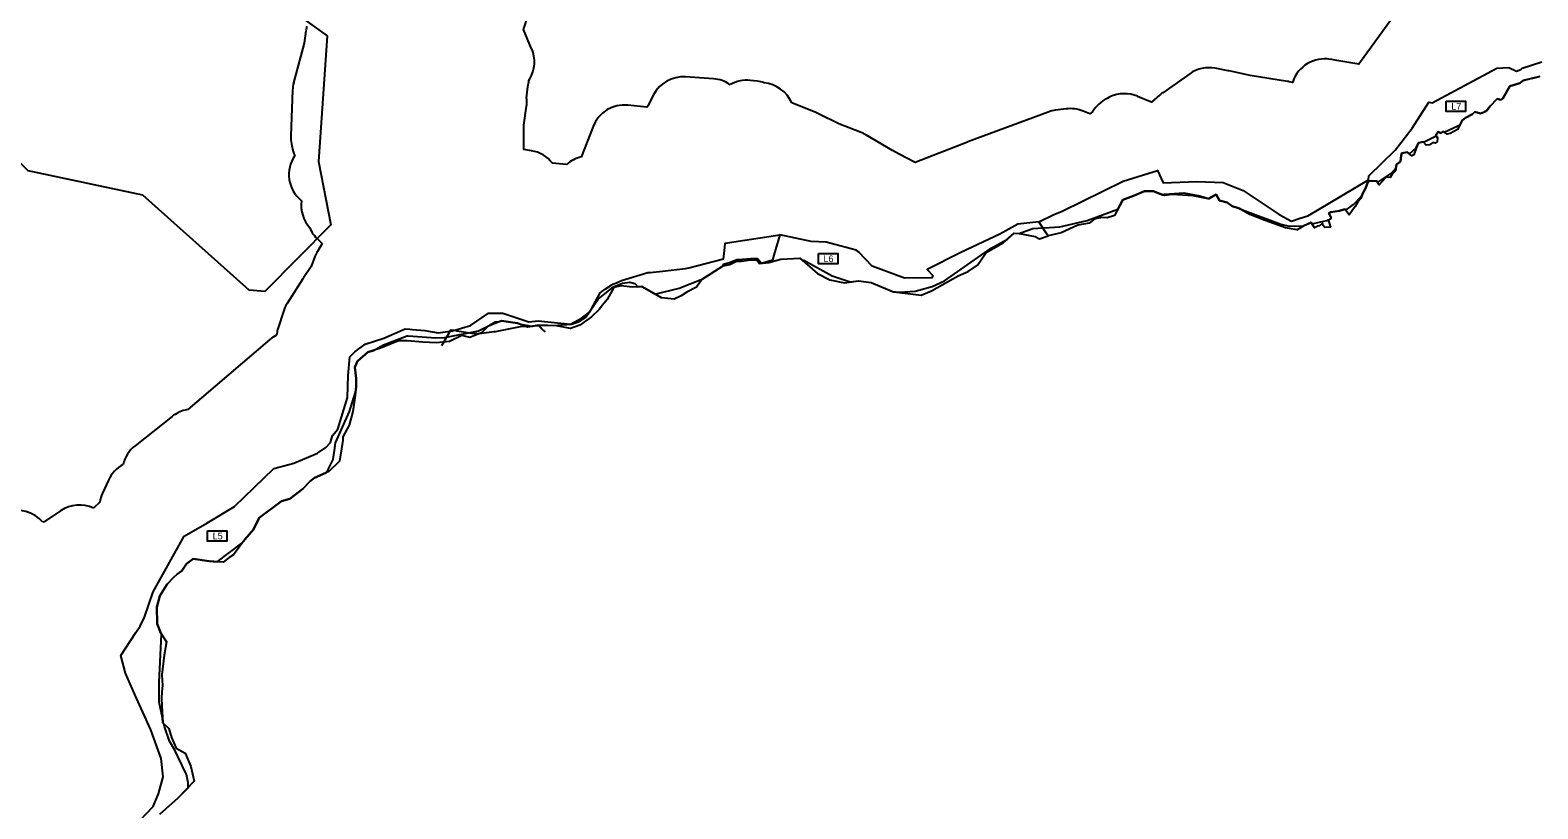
# Model space of a CAD drawing. Extents: x -547623 to -532764, y -1096714 to -1086523.
# Drawn here: x -544003 to -541756, y -1095554 to -1094393 of the extents above; entities that cross this region are included whole.
import ezdxf

# ---------------------------------------------------------------- set-up
doc = ezdxf.new("R2010")
doc.units = 0
for name, color, linetype in [('Vrstva 22', 7, 'Continuous'), ('Vrstva 23', 7, 'Continuous'), ('Vrstva 32', 7, 'Continuous'), ('Vrstva 33', 7, 'Continuous'), ('Vrstva 36', 7, 'Continuous')]:
    doc.layers.add(name, color=color, linetype=linetype)

msp = doc.modelspace()

# ---------------------------------------------------------------- linework, layer by layer
at = {"layer": 'Vrstva 22'}
for points in [[(-543560.2, -1094401.9), (-543572.9, -1094589), (-543554.8, -1094683.6), (-543653.3, -1094783), (-543676.2, -1094781), (-543835.1, -1094639.3), (-544005.7, -1094603.1), (-544067, -1094543.3), (-544325.4, -1094603.1), (-544346.2, -1094593.4), (-544353.7, -1094422.2), (-544152.6, -1094360.6), (-544163.2, -1094317.9), (-544141.9, -1094287.2), (-544146.7, -1094205.7), (-543991.6, -1094091.9), (-543560.2, -1094401.9)], [(-543809.7, -1095562), (-543782.5, -1095538.1), (-543767.4, -1095522.3), (-543767.1, -1095514.9), (-543769.7, -1095502.6), (-543782.6, -1095476), (-543787.2, -1095466.4), (-543795.3, -1095453.2), (-543802.7, -1095431.2), (-543803.6, -1095427), (-543804.9, -1095425.8), (-543805.5, -1095418), (-543810.4, -1095394.8), (-543810.6, -1095367.2), (-543810.5, -1095365.7), (-543807.1, -1095293.4), (-543808.1, -1095291.9), (-543813.3, -1095278.2), (-543814.2, -1095253.2), (-543809.7, -1095236.4), (-543798.5, -1095218.8), (-543789.3, -1095209), (-543783.6, -1095204.3), (-543776.7, -1095199.2), (-543769.6, -1095188.9), (-543759.7, -1095181.3), (-543736.2, -1095184.9), (-543723.9, -1095185.6), (-543687.1, -1095158), (-543683.1, -1095152.5), (-543670.1, -1095137.4), (-543661.4, -1095120), (-543628, -1095095.2), (-543615.8, -1095091.8), (-543596.4, -1095077), (-543585.6, -1095065.3), (-543578.9, -1095060.6), (-543562.3, -1095053.3), (-543558.8, -1095048.2), (-543551, -1095033), (-543549.4, -1095020), (-543547.9, -1095008.3), (-543527, -1094961.6), (-543517.8, -1094932.9), (-543516.9, -1094925.6), (-543517.1, -1094912.3), (-543518.7, -1094895.4), (-543515, -1094886.5), (-543499.6, -1094873.2), (-543491.3, -1094870.7), (-543476.1, -1094862.1), (-543440.9, -1094849), (-543440.8, -1094848.8), (-543439.3, -1094848.9), (-543398.1, -1094851.9), (-543385, -1094851.2), (-543334.8, -1094841.6), (-543317.9, -1094832.8), (-543309.1, -1094828.2), (-543303.3, -1094827.7), (-543300.5, -1094826.6), (-543276.6, -1094829.8), (-543272.1, -1094831.6), (-543255.6, -1094834.5), (-543254, -1094834.5), (-543244.5, -1094832.9), (-543223.2, -1094833.6), (-543196.2, -1094831.5), (-543185.8, -1094828.2), (-543174.6, -1094821.1), (-543156.1, -1094794.3), (-543133.5, -1094776.1), (-543120, -1094770.4), (-543109, -1094768.9), (-543101.4, -1094771), (-543097.4, -1094775.8), (-543091.3, -1094775.4), (-543074, -1094785.5), (-543071.6, -1094786.8), (-543035.5, -1094777.7), (-543000.4, -1094763.9), (-542970, -1094744.8), (-542959.8, -1094742.5), (-542950.1, -1094737.7), (-542942.8, -1094737.7), (-542929.1, -1094735.8), (-542919.9, -1094736.3), (-542915.9, -1094741.3), (-542901.9, -1094739.7), (-542883.9, -1094734.4), (-542855.6, -1094733.1), (-542852.6, -1094735.8), (-542848.8, -1094736.5), (-542807.3, -1094759.3), (-542780.5, -1094768.5), (-542768.2, -1094766.8), (-542749.4, -1094769.5), (-542717.7, -1094782.6), (-542707.1, -1094783.6), (-542683.6, -1094782.4), (-542658.5, -1094775.4), (-542640.1, -1094767.1), (-542570.7, -1094718), (-542546, -1094704.6), (-542536.2, -1094696), (-542528.8, -1094696.6), (-542528.6, -1094696.6), (-542521.1, -1094693.2), (-542508.7, -1094689.1), (-542468, -1094686.4), (-542427.4, -1094676.8), (-542381.9, -1094660), (-542374.5, -1094646.2), (-542358.2, -1094640.2), (-542342.1, -1094633.3), (-542329.2, -1094633.2), (-542315.4, -1094638.5), (-542312.3, -1094637.9), (-542283.6, -1094635.9), (-542259.4, -1094640.1), (-542246.5, -1094644.1), (-542245.9, -1094644.3), (-542235.2, -1094638.1), (-542230.4, -1094647.4), (-542218.9, -1094650.2), (-542211.2, -1094655.4), (-542200.6, -1094659.3), (-542199.9, -1094659.7), (-542138.7, -1094682.6), (-542126.6, -1094685.4), (-542105.5, -1094684.7), (-542103, -1094684.1), (-542093.8, -1094680.2), (-542092.7, -1094681.9), (-542070.3, -1094677), (-542065, -1094674.3), (-542063.8, -1094672.9), (-542067.4, -1094666.2), (-542064.2, -1094664.5), (-542051.3, -1094662.4), (-542043.3, -1094659.9), (-542042, -1094661.6), (-542030.4, -1094653.3), (-542018.3, -1094640.4), (-542016.8, -1094636.1), (-542013.1, -1094630.1), (-542008.5, -1094618.9), (-542004.4, -1094618), (-541996, -1094618.6), (-541994.7, -1094620.6), (-541973.8, -1094606.7), (-541967.4, -1094599.2), (-541966.4, -1094593.4), (-541960.5, -1094589.2), (-541959.4, -1094580.1), (-541958.3, -1094576.7), (-541950.4, -1094575), (-541947.3, -1094577.7), (-541937, -1094568.6), (-541933.5, -1094561.4), (-541926.5, -1094560), (-541926.2, -1094560.4), (-541907.4, -1094550.6), (-541907.8, -1094549.7), (-541904.6, -1094544.8), (-541900.4, -1094546.9), (-541897.1, -1094544.2), (-541895.6, -1094545.2), (-541874.9, -1094536), (-541871.8, -1094534.3), (-541868.6, -1094528.1), (-541863.7, -1094523.8), (-541853.3, -1094518.3), (-541849.9, -1094515.2), (-541841.5, -1094517.4), (-541838.8, -1094516.6), (-541833.1, -1094513.6), (-541832, -1094512.9), (-541826.9, -1094506.6), (-541816.2, -1094495.8), (-541810.8, -1094497.1), (-541807.8, -1094495.3), (-541797.4, -1094476.6), (-541782.6, -1094472.5), (-541777.7, -1094468.4), (-541753.1, -1094462.3)]]:
    msp.add_lwpolyline(points, dxfattribs=at)
at = {"layer": 'Vrstva 23'}
for p, q in [((-542217.2, -1094453.9), (-542236.8, -1094450.2)), ((-543259.5, -1094468.2), (-543258.2, -1094466)), ((-542984.4, -1094465.9), (-543026.1, -1094463)), ((-542919.1, -1094469.5), (-542929.2, -1094468.4)), ((-542274.6, -1094458.3), (-542314.9, -1094486.5)), ((-543611.7, -1094482.6), (-543614.5, -1094551)), ((-543073.8, -1094489.6), (-543082.4, -1094506.1)), ((-542393.5, -1094492.9), (-542397.7, -1094495)), ((-543083.5, -1094508.3), (-543111.9, -1094505.3)), ((-542831.8, -1094516), (-542867.8, -1094501.8)), ((-542485.7, -1094515.4), (-542605.1, -1094559.9)), ((-542458.9, -1094510.7), (-542474.5, -1094512.7)), ((-543163.8, -1094536.8), (-543181.7, -1094582.4)), ((-543613.5, -1094562.9), (-543612.5, -1094567.8)), ((-543203.3, -1094593.4), (-543224.6, -1094591.4)), ((-543596.3, -1094763.8), (-543620, -1094800.9)), ((-543625.4, -1094812.5), (-543633.3, -1094837.1)), ((-543635.3, -1094845.9), (-543635.5, -1094847.9)), ((-543389.2, -1094863.5), (-543375.6, -1094839.6)), ((-543374.2, -1094839.9), (-543367.8, -1094841.1)), ((-543366.2, -1094841.4), (-543344.4, -1094844.9)), ((-543329.5, -1094845.1), (-543311.7, -1094842.6)), ((-543791.1, -1094968.9), (-543846.4, -1095012.6)), ((-543886.1, -1095063.9), (-543895, -1095083.5)), ((-543898.9, -1095096.6), (-543908.3, -1095105.7))]:
    msp.add_line(p, q, dxfattribs=at)
for points in [[(-543255.4, -1094421.1), (-543267.6, -1094392.3), (-543259.9, -1094369.4), (-543237.1, -1094310), (-543199.4, -1094263.4)], [(-541968.6, -1094369.7), (-542022.6, -1094444.1), (-542055.6, -1094438.5), (-542065.1, -1094436.8)], [(-543591.8, -1094394.1), (-543594.2, -1094412.7), (-543610.1, -1094471.6)], [(-543262.8, -1094495.6), (-543262.9, -1094494.6), (-543260.9, -1094477.3), (-543259.7, -1094470.2)], [(-542128.8, -1094469.8), (-542184.5, -1094460.8), (-542216.1, -1094454.1)], [(-542121, -1094470.2), (-542121.4, -1094471.3), (-542126.5, -1094470.2)], [(-542319.6, -1094490.1), (-542331.4, -1094500.6), (-542333.1, -1094500.2), (-542352.4, -1094492)], [(-543255.8, -1094573.1), (-543267.1, -1094571.2), (-543267, -1094534.9), (-543263.1, -1094506.7)], [(-542764.5, -1094545.9), (-542797.8, -1094532.9), (-542827.7, -1094517.8)], [(-542419.4, -1094515), (-542423.7, -1094518.2), (-542433.5, -1094514.1)], [(-542605.8, -1094560.1), (-542683.8, -1094590.4), (-542707.7, -1094578.1), (-542717.5, -1094572.7), (-542757.5, -1094549.3)], [(-543567.7, -1094711.2), (-543574.6, -1094723.1)], [(-543573.8, -1094705.5), (-543567.7, -1094711.2)], [(-543578.3, -1094730.8), (-543583.8, -1094745.6), (-543595.4, -1094762.4)], [(-543309.4, -1094842.2), (-543271.9, -1094835.1), (-543245.3, -1094833.5), (-543244.1, -1094833.6)], [(-543645.4, -1094854.4), (-543767.8, -1094958.6), (-543772, -1094959.6)], [(-543957.5, -1095109.6), (-543981.8, -1095126.1), (-543983.9, -1095126.8)]]:
    msp.add_lwpolyline(points, dxfattribs=at)
for centre, start, end in [((-543542.2, -1094400.5), 164.5282, 172.6054), ((-543301.3, -1094440.7), 329.6624, 23.1076), ((-542246, -1094499.3), 79.3857, 124.8843), ((-542073.6, -1094486.1), 80.1672, 161.466), ((-543561.8, -1094484.6), 164.8941, 177.7234), ((-543309.1, -1094462.3), 350.8576, 353.2391), ((-543029.5, -1094512.9), 86.0355, 152.2658), ((-542987.8, -1094515.8), 55.4841, 86.0355), ((-542934.8, -1094518), 83.5602, 119.6147), ((-542924.7, -1094519.2), 71.6373, 83.5602), ((-542913.8, -1094521.5), 23.2461, 84.4318), ((-542226.4, -1094503), 78.0594, 79.3857), ((-542136.8, -1094519.1), 78.0491, 80.7914), ((-543312.6, -1094499.8), 352.0607, 4.8264), ((-542376.2, -1094540.1), 115.5839, 149.8873), ((-542371.9, -1094538), 67.0903, 115.5839), ((-542286.3, -1094527.5), 124.8843, 131.6661), ((-543117.3, -1094555), 83.8584, 158.6538), ((-543038.2, -1094529.4), 152.2658, 155.0921), ((-542850.2, -1094562.5), 63.2846, 68.4439), ((-542468.2, -1094562.3), 97.2381, 110.4098), ((-542452.6, -1094560.3), 67.5248, 97.2381), ((-543564.5, -1094553), 177.7234, 191.3997), ((-542782.7, -1094592.4), 59.7243, 68.6544), ((-542587.7, -1094606.7), 110.4098, 111.1963), ((-543567.2, -1094608.4), 145.4057, 231.4006), ((-543563.5, -1094557.9), 191.3997, 206.2085), ((-543263.8, -1094622.4), 38.296, 80.7669), ((-543170.5, -1094631.1), 102.8626, 130.9213), ((-543548.9, -1094654.3), 172.1678, 222.2602), ((-543539.6, -1094669.1), 202.1046, 226.8144), ((-543531.5, -1094748.3), 149.6642, 159.533), ((-543554.2, -1094790.7), 145.5015, 147.4878), ((-543577.8, -1094827.8), 147.4878, 162.2097), ((-543203.3, -1094804.7), 215.289, 230.2251), ((-543613, -1094892.5), 116.7258, 130.3971), ((-543585.7, -1094852.4), 162.2097, 172.515), ((-543364.7, -1094790.8), 257.4035, 259.0155), ((-543358.3, -1094792), 259.0155, 260.8104), ((-543336.4, -1094795.6), 260.8104, 277.9904), ((-543318.6, -1094793.1), 277.9904, 280.6932), ((-543760.1, -1095008.2), 103.7608, 128.3056), ((-543815.4, -1095051.9), 128.3056, 166.8865), ((-543840.6, -1095084.6), 118.0812, 155.5494), ((-543929.5, -1095151), 64.9086, 124.0814), ((-543849.5, -1095104.2), 155.5494, 171.3209), ((-544022.4, -1095158.7), 39.675, 109.7016)]:
    msp.add_arc(centre, 50, start, end, dxfattribs=at)
at = {"layer": 'Vrstva 32'}
for points in [[(-542897.2, -1094738.3), (-542883.9, -1094734.4), (-542855.6, -1094733.1), (-542829.3, -1094756.2), (-542811, -1094765.6), (-542789.3, -1094769.8), (-542768.2, -1094766.8), (-542749.4, -1094769.5), (-542715.9, -1094783.3), (-542698.7, -1094785.5), (-542674.7, -1094788.2), (-542659.7, -1094781.6), (-542619.8, -1094759.5), (-542604.6, -1094753.2), (-542591, -1094743.7), (-542577.8, -1094724.7), (-542552.5, -1094710.2), (-542536.2, -1094696), (-542528.8, -1094696.6), (-542505.2, -1094700.8), (-542498.6, -1094704.4), (-542485.8, -1094699.8), (-542487, -1094697.9)], [(-542816.4, -1094709.2), (-542838.9, -1094708.1), (-542885.7, -1094698.4), (-542894.4, -1094728.5)], [(-542557.4, -1094697.3), (-542616, -1094724.6), (-542665.7, -1094750), (-542657.7, -1094759.1), (-542659.1, -1094762.4), (-542699.6, -1094763.1), (-542747.8, -1094745.3), (-542767.8, -1094724.4)], [(-542487, -1094697.9), (-542499.5, -1094678.9), (-542530.7, -1094682.6), (-542557.4, -1094697.3)], [(-542771.6, -1094721.4), (-542816.4, -1094709.2)], [(-542767.8, -1094724.4), (-542771.6, -1094721.4)], [(-542896.5, -1094736), (-542897.2, -1094738.3)], [(-542894.4, -1094728.5), (-542896.5, -1094736)]]:
    msp.add_lwpolyline(points, dxfattribs=at)
at = {"layer": 'Vrstva 33'}
msp.add_line((-542771.6, -1094721.4), (-542767.8, -1094724.4), dxfattribs=at)
for points in [[(-541752.8, -1094462.2), (-541777.7, -1094468.4), (-541782.6, -1094472.5), (-541797.4, -1094476.6), (-541807.8, -1094495.3), (-541810.8, -1094497.1), (-541816.2, -1094495.8), (-541826.9, -1094506.6), (-541833.8, -1094515.2), (-541841.5, -1094517.4), (-541849.9, -1094515.2), (-541853.3, -1094518.3), (-541863.7, -1094523.8), (-541868.6, -1094528.1), (-541875.4, -1094541.5), (-541886.4, -1094547.2), (-541891.2, -1094548.2), (-541897.1, -1094544.2), (-541900.4, -1094546.9), (-541904.6, -1094544.8), (-541907.8, -1094549.7), (-541905.6, -1094553.9), (-541906.1, -1094559.9), (-541909, -1094561.7), (-541912.5, -1094560.6), (-541917.1, -1094564.2), (-541922.5, -1094564.6), (-541926.5, -1094560), (-541933.5, -1094561.4), (-541937.4, -1094569.3), (-541940.6, -1094579.2), (-541943.8, -1094580.7), (-541950.4, -1094575), (-541958.3, -1094576.7), (-541959.4, -1094580.1), (-541960.5, -1094589.2), (-541966.4, -1094593.4), (-541968.1, -1094603), (-541972.8, -1094607.9), (-541976.1, -1094613), (-541981.7, -1094612.6), (-541987.8, -1094619.1), (-541992.5, -1094624), (-541996, -1094618.6), (-542004.4, -1094618), (-542008.5, -1094618.9), (-542013.1, -1094630.1), (-542016.8, -1094636.1), (-542019.7, -1094644.4), (-542024, -1094649.2), (-542028.2, -1094656.2), (-542037, -1094668.6), (-542043.3, -1094659.9), (-542051.3, -1094662.4), (-542064.2, -1094664.5), (-542067.4, -1094666.2), (-542063.8, -1094672.9), (-542067.9, -1094677.6), (-542066.5, -1094681.9), (-542064.9, -1094687.1), (-542073.3, -1094687.2), (-542075.6, -1094684.6), (-542077, -1094681.1), (-542081.3, -1094684.7), (-542083.8, -1094685.3), (-542088.7, -1094687.9), (-542093.8, -1094680.2), (-542104.5, -1094684.8), (-542114.7, -1094691), (-542131.9, -1094688), (-542149.7, -1094681.3), (-542162.3, -1094677.2), (-542185, -1094668.2), (-542200.6, -1094659.3), (-542211.2, -1094655.4), (-542218.9, -1094650.2), (-542230.4, -1094647.4), (-542235.2, -1094638.1), (-542247, -1094644.9), (-542269.5, -1094640.3), (-542300.6, -1094638.3), (-542312.1, -1094639.8), (-542329.2, -1094633.2), (-542342.1, -1094633.3), (-542358.2, -1094640.2), (-542374.5, -1094646.2), (-542386.9, -1094669.3), (-542397.5, -1094673), (-542404.8, -1094672.7), (-542416.3, -1094674.5), (-542424.6, -1094680.8), (-542441.2, -1094684), (-542466, -1094695.6), (-542485.8, -1094699.8), (-542487, -1094697.9), (-542499.5, -1094678.9), (-542478.2, -1094668.6), (-542464.5, -1094662.9), (-542373.9, -1094618.3), (-542322.7, -1094602.4), (-542314, -1094620.9), (-542263.8, -1094618.7), (-542224.6, -1094620.3), (-542194.8, -1094632.4), (-542141.4, -1094668.2), (-542123, -1094678), (-542110.2, -1094673.6), (-542098.7, -1094669.8), (-542086.7, -1094663.3), (-542008.4, -1094616.4), (-542007.8, -1094610.3), (-541968.4, -1094572.1), (-541943.1, -1094539.4), (-541918.5, -1094500.8), (-541913.5, -1094501.7), (-541816.8, -1094450.1), (-541799.1, -1094449.2), (-541787.8, -1094454.6), (-541781.4, -1094451.8), (-541779, -1094449.9), (-541750, -1094440.5)], [(-543848.7, -1095581), (-543819.4, -1095550.1), (-543811.7, -1095531.6), (-543804.7, -1095506), (-543807.8, -1095478.9), (-543823, -1095436.2), (-543846.8, -1095383.2), (-543860.5, -1095351.7), (-543867.8, -1095325.5), (-543845.3, -1095290.9), (-543839, -1095281.8), (-543832.3, -1095268), (-543819.5, -1095230.3), (-543773.1, -1095147.6), (-543739.7, -1095127.9), (-543698.2, -1095103.1), (-543639.6, -1095046.6), (-543609.6, -1095038.4), (-543574.8, -1095023.9), (-543562.4, -1095015.2), (-543555.4, -1095007.6), (-543552.3, -1094997.4), (-543544.1, -1094988.2), (-543530.1, -1094941), (-543528.9, -1094908.1), (-543526.4, -1094880.4), (-543519.1, -1094872.7), (-543503.6, -1094861.5), (-543475.7, -1094852.5), (-543443.9, -1094838.5), (-543436.8, -1094839.1), (-543433, -1094839.4), (-543414.6, -1094840.9), (-543394.8, -1094844.6), (-543373.5, -1094841.4), (-543346.7, -1094833.7), (-543319.8, -1094815.3), (-543298.5, -1094815), (-543259.6, -1094827.8), (-543245.5, -1094826.3), (-543197.3, -1094831.4), (-543181, -1094822.7), (-543169.1, -1094813.4), (-543166.8, -1094809.4), (-543153.2, -1094784.7), (-543145.9, -1094779.2), (-543135.9, -1094772.9), (-543134.2, -1094772.1), (-543129.2, -1094770), (-543121.7, -1094766.4), (-543082.1, -1094754.7), (-543078.8, -1094754.3), (-543060.6, -1094752.4), (-543026.3, -1094748.7), (-543021.1, -1094747.3), (-542969.6, -1094734.3), (-542969.2, -1094730.6), (-542967.7, -1094717), (-542967, -1094710.6), (-542885.7, -1094698.4), (-542894.4, -1094728.5), (-542896.5, -1094736), (-542912.9, -1094741.3), (-542918.8, -1094734.2), (-542928.8, -1094734.1), (-542941.1, -1094735.1), (-542949.8, -1094735.6), (-542960.3, -1094740), (-542969.8, -1094742.6), (-542970, -1094744.8), (-543001.6, -1094764.7), (-543009.6, -1094776.4), (-543024, -1094783.6), (-543032.7, -1094789.2), (-543043.2, -1094794.3), (-543062, -1094792.2), (-543074, -1094785.5), (-543091.3, -1094775.4), (-543105.3, -1094776.3), (-543122.3, -1094774.2), (-543132.7, -1094776.9), (-543143, -1094794.8), (-543149.6, -1094803.2), (-543154.8, -1094809.7), (-543166.3, -1094820.5), (-543183.4, -1094832.9), (-543197.3, -1094838), (-543218.6, -1094833.8), (-543244.5, -1094832.9), (-543261.4, -1094835.8), (-543276.6, -1094829.8), (-543300.5, -1094826.6), (-543320.6, -1094834.8), (-543330.4, -1094844.4), (-543332.8, -1094845.3), (-543347.7, -1094851.2), (-543359.4, -1094848.4), (-543377.9, -1094857.3), (-543397.8, -1094859.1), (-543417.5, -1094858.5), (-543440.8, -1094856.2), (-543454.1, -1094856.1), (-543473, -1094864.5), (-543482.1, -1094867.9), (-543499.6, -1094873.2), (-543515, -1094886.5), (-543518.7, -1094895.4), (-543517.1, -1094912.3), (-543516.9, -1094925.6), (-543518.8, -1094940.6), (-543521.8, -1094961.8), (-543527.5, -1094981.8), (-543536.8, -1094999.4), (-543536.8, -1095004.5), (-543538.8, -1095017.2), (-543541.9, -1095035.8), (-543557.7, -1095051.3), (-543578.9, -1095060.6), (-543585.6, -1095065.3), (-543596.4, -1095077), (-543615.8, -1095091.8), (-543628, -1095095.2), (-543661.4, -1095120), (-543670.1, -1095137.4), (-543683.1, -1095152.5), (-543699.8, -1095175.4), (-543706.2, -1095179.2), (-543715.2, -1095186.1), (-543736.2, -1095184.9), (-543759.7, -1095181.3), (-543769.6, -1095188.9), (-543776.7, -1095199.2), (-543783.6, -1095204.3), (-543789.3, -1095209), (-543798.5, -1095218.8), (-543809.7, -1095236.4), (-543814.2, -1095253.2), (-543813.3, -1095278.2), (-543808.1, -1095291.9), (-543799.7, -1095304.8), (-543803.3, -1095324.9), (-543806.7, -1095354.3), (-543805.5, -1095370), (-543806.5, -1095379.5), (-543807.1, -1095389.1), (-543806.8, -1095400.3), (-543804.9, -1095425.8), (-543795.9, -1095433.9), (-543792, -1095447.4), (-543785.4, -1095463.3), (-543771.9, -1095470.7), (-543763.2, -1095490.5), (-543758.3, -1095512.8), (-543782.5, -1095538.1), (-543809.7, -1095562)]]:
    msp.add_lwpolyline(points, dxfattribs=at)
at = {"layer": 'Vrstva 36'}
for points in [[(-541892.3, -1094499.1), (-541863.7, -1094499.1), (-541863.7, -1094514.5), (-541892.3, -1094514.5)], [(-542827.9, -1094726.2), (-542799.2, -1094726.2), (-542799.2, -1094741.7), (-542827.9, -1094741.7)], [(-543738.3, -1095139.4), (-543709.7, -1095139.4), (-543709.7, -1095154.9), (-543738.3, -1095154.9)]]:
    msp.add_lwpolyline(points, close=True, dxfattribs=at)

# ---------------------------------------------------------------- texts
for s, p in [('L7', (-541884.8, -1094511.8)), ('L6', (-542820.5, -1094739)), ('L5', (-543730.7, -1095152.2))]:
    msp.add_text(s, height=10, dxfattribs=at).set_placement(p)

doc.saveas('drawing.dxf')
